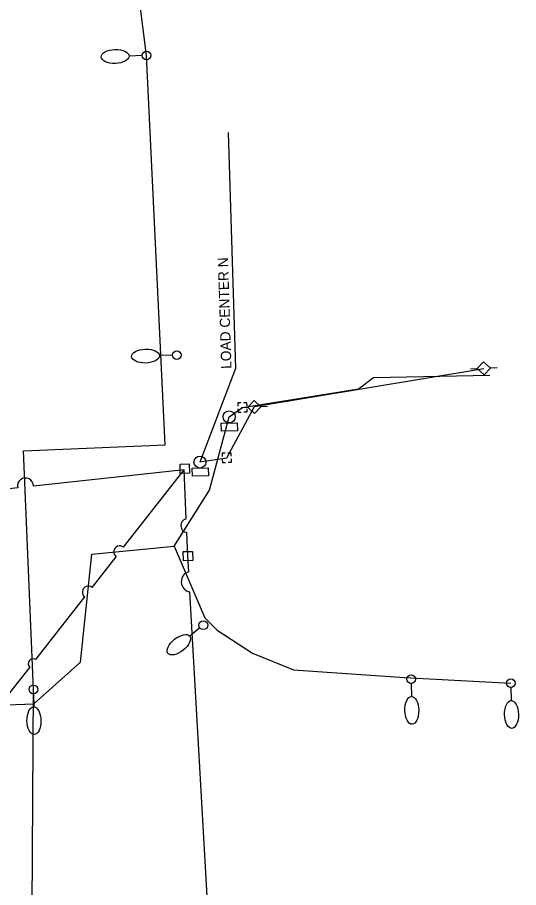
# Model space of a CAD drawing. Extents: x 925407 to 930994, y 604905 to 637063.
# Drawn here: x 929927.5 to 930200.5, y 610501.6 to 610975.5 of the extents above; entities that cross this region are included whole.
import ezdxf

# ---------------------------------------------------------------- set-up
doc = ezdxf.new("R2010")
doc.units = 0
for name, color, linetype in [('ActivePointCell_dp', 7, 'Continuous'), ('Conduit', 7, 'Continuous'), ('ConduitDB', 7, 'Continuous'), ('ConduitOT', 7, 'Continuous'), ('LoadCenter', 7, 'Continuous'), ('LoadCenter_ep', 7, 'Continuous'), ('PoleElec_ep', 7, 'Continuous'), ('PoleLight_ep', 7, 'Continuous'), ('PullBox', 7, 'Continuous')]:
    doc.layers.add(name, color=color, linetype=linetype)

msp = doc.modelspace()

# ---------------------------------------------------------------- linework, layer by layer
at = {"layer": 'ActivePointCell_dp'}
msp.add_line((930042.23, 610912.84), (930046.23, 610784.25), dxfattribs=at)
msp.add_lwpolyline([(930046.23, 610784.25), (930026.97, 610733.37)], dxfattribs=at)
at = {"layer": 'Conduit'}
for p, q in [((929997.8, 610954.73), (929969.71, 611176.28)), ((930007.93, 610742.68), (929997.8, 610954.73)), ((929930.84, 610739.51), (930007.93, 610742.68)), ((929936.2, 610609.56), (929930.84, 610739.51)), ((929968.14, 610683.12), (930012.94, 610687.48)), ((930012.94, 610687.48), (930029.62, 610648.47)), ((929961.8, 610624.34), (929968.14, 610683.12)), ((930029.62, 610648.47), (930036.37, 610641.82)), ((930036.37, 610641.82), (930055.61, 610629.26)), ((930055.61, 610629.26), (930077.85, 610620.17)), ((929936.49, 610601.64), (929961.8, 610624.34)), ((930077.85, 610620.17), (930138.42, 610616.12)), ((930138.42, 610616.12), (930196.34, 610612.96)), ((929935.24, 610442.43), (929936.2, 610609.56)), ((929711.58, 610593.62), (929936.49, 610601.64))]:
    msp.add_line(p, q, dxfattribs=at)
for points in [[(930113.27, 610773.21), (930113.27, 610773.21), (930121.4, 610779.38), (930184.79, 610780.71)], [(930050.05, 610763.09), (930050.05, 610763.09), (930113.27, 610773.21)], [(930042.85, 610757.95), (930042.85, 610757.95), (930050.05, 610763.09)], [(930012.94, 610687.48), (930032.16, 610717.96), (930042.85, 610757.95)]]:
    msp.add_lwpolyline(points, dxfattribs=at)
at = {"layer": 'ConduitDB'}
for p, q in [((930018.26, 610729.14), (929936.26, 610720.27)), ((929985.33, 610686.97), (930018.26, 610729.14)), ((929927.69, 610719.34), (929817.94, 610707.47)), ((929968.24, 610665.09), (929981.31, 610681.83)), ((930020.89, 610673.64), (930020.41, 610682.13)), ((930035.34, 610417.86), (930021.51, 610662.68)), ((929937.53, 610625.76), (929964.23, 610659.96)), ((929922.8, 610606.91), (929934.22, 610621.53))]:
    msp.add_line(p, q, dxfattribs=at)
for centre, radius, start, end in [((929931.92, 610720.35), 4.34, 358.9381, 193.2638), ((929983.26, 610684.45), 3.26, 50.6705, 233.352), ((930022.39, 610668.23), 5.62, 105.4594, 261.004), ((929966.17, 610662.58), 3.26, 50.5529, 233.4697), ((929936.12, 610623.45), 2.71, 58.7312, 225.2914)]:
    msp.add_arc(centre, radius, start, end, dxfattribs=at)
at = {"layer": 'ConduitOT'}
for p, q in [((930056.68, 610763.54), (930181.58, 610784.38)), ((930041.52, 610735.7), (930056.68, 610763.54)), ((930026.89, 610733.44), (930041.52, 610735.7)), ((930019.49, 610702.37), (930018.26, 610729.14)), ((930020.41, 610682.13), (930019.82, 610695.01))]:
    msp.add_line(p, q, dxfattribs=at)
msp.add_arc((930020.24, 610698.72), 3.73, 101.7099, 263.539, dxfattribs=at)
at = {"layer": 'LoadCenter'}
for p, q in [((930022.7, 610729.98), (930031.42, 610730.21)), ((930022.81, 610725.62), (930022.7, 610729.98)), ((930031.42, 610730.21), (930031.53, 610725.84)), ((930031.53, 610725.84), (930022.81, 610725.62))]:
    msp.add_line(p, q, dxfattribs=at)
msp.add_circle((930026.97, 610733.37), 3.27, dxfattribs=at)
at = {"layer": 'LoadCenter_ep'}
for p, q in [((930038.57, 610754.56), (930047.29, 610754.79)), ((930038.68, 610750.2), (930038.57, 610754.56)), ((930047.29, 610754.79), (930047.41, 610750.42)), ((930047.41, 610750.42), (930038.68, 610750.2))]:
    msp.add_line(p, q, dxfattribs=at)
msp.add_circle((930042.85, 610757.95), 3.27, dxfattribs=at)
at = {"layer": 'PoleElec_ep'}
for p, q in [((930174.32, 610784.16), (930177.96, 610784.27)), ((930188.83, 610784.61), (930185.19, 610784.49)), ((930049.31, 610763.1), (930052.95, 610763.21)), ((930063.82, 610763.55), (930060.18, 610763.44))]:
    msp.add_line(p, q, dxfattribs=at)
for points in [[(930177.96, 610784.27), (930181.69, 610780.77), (930185.19, 610784.49), (930181.46, 610787.99), (930177.96, 610784.27)], [(930052.95, 610763.21), (930056.68, 610759.72), (930060.18, 610763.44), (930056.45, 610766.94), (930052.95, 610763.21)]]:
    msp.add_lwpolyline(points, dxfattribs=at)
at = {"layer": 'PoleLight_ep'}
for p, q in [((929995.43, 610954.66), (929988.34, 610954.44)), ((930011.95, 610791.52), (930004.86, 610791.3)), ((930026.94, 610643), (930021.38, 610638.59)), ((930142.05, 610612.81), (930142.18, 610605.71)), ((930196.38, 610610.59), (930196.52, 610603.5)), ((929936.24, 610607.2), (929936.38, 610600.1))]:
    msp.add_line(p, q, dxfattribs=at)
for centre in [(929997.8, 610954.73), (930014.32, 610791.59), (930028.79, 610644.47), (930142.01, 610615.17), (930196.34, 610612.96), (929936.2, 610609.56)]:
    msp.add_circle(centre, 2.37, dxfattribs=at)
for centre, major_axis in [((929980.77, 610954.2), (-7.57, -0.24)), ((929997.29, 610791.07), (-7.57, -0.24)), ((930015.45, 610633.88), (-5.93, -4.71)), ((930142.33, 610598.14), (0.14, -7.57)), ((929936.52, 610592.53), (0.14, -7.57)), ((930196.66, 610595.93), (0.14, -7.57))]:
    msp.add_ellipse(centre, major_axis=major_axis, ratio=0.5, dxfattribs=at)
at = {"layer": 'PullBox'}
for p, q in [((930016.12, 610732.21), (930021.12, 610732.34)), ((930016.25, 610727.21), (930016.12, 610732.21)), ((930021.12, 610732.34), (930021.25, 610727.34)), ((930021.25, 610727.34), (930016.25, 610727.21)), ((930017.85, 610684.57), (930022.85, 610684.7)), ((930017.98, 610679.57), (930017.85, 610684.57)), ((930022.85, 610684.7), (930022.98, 610679.7)), ((930022.98, 610679.7), (930017.98, 610679.57))]:
    msp.add_line(p, q, dxfattribs=at)
for points in [[(930049.2, 610765.57), (930047.52, 610765.52), (930047.58, 610763.76)], [(930052.58, 610763.91), (930052.52, 610765.67), (930050.75, 610765.62)], [(930047.62, 610762.26), (930047.68, 610760.53), (930049.35, 610760.58)], [(930050.9, 610760.63), (930052.67, 610760.68)], [(930052.67, 610760.68), (930052.62, 610762.41)], [(930040.67, 610738.18), (930038.99, 610738.13), (930039.05, 610736.37)], [(930044.04, 610736.52), (930043.99, 610738.28), (930042.22, 610738.23)], [(930039.09, 610734.87), (930039.14, 610733.14), (930040.82, 610733.19)], [(930042.37, 610733.24), (930044.14, 610733.29)], [(930044.14, 610733.29), (930044.09, 610735.02)]]:
    msp.add_lwpolyline(points, dxfattribs=at)

# ---------------------------------------------------------------- texts
at = {"layer": 'ActivePointCell_dp'}
msp.add_text('LOAD CENTER N', height=5.6, rotation=91.7832, dxfattribs=at).set_placement((930044.13, 610784.18))

doc.saveas('drawing.dxf')
